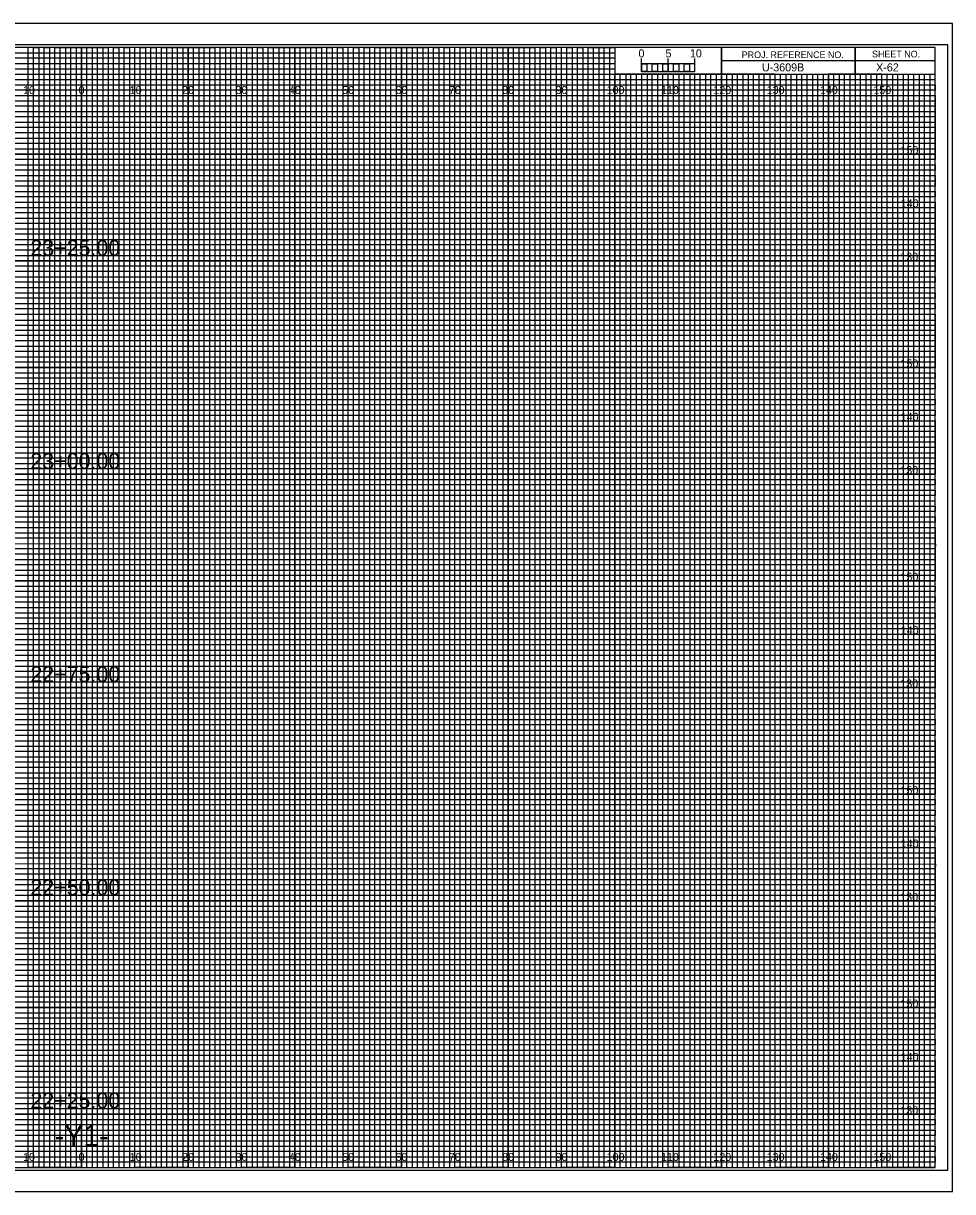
# Model space of a CAD drawing. Extents: x -13 to 323, y -5 to 2634.
# Drawn here: x 149.1 to 323.3, y 2195.5 to 2414.5 of the extents above; entities that cross this region are included whole.
import ezdxf

# ---------------------------------------------------------------- set-up
doc = ezdxf.new("R2010")
doc.units = 0
for name, color, linetype in [('Exist Cross Section Cell', 7, 'Continuous'), ('Exist XS Center Line Elevation Label', 7, 'Continuous'), ('Exist XS Ground Line', 7, 'Continuous'), ('Prop CMT Pvmt Course 1', 7, 'Continuous'), ('Prop CMT Pvmt Course 1 Wedge', 7, 'Continuous'), ('Prop CMT Pvmt Course 2', 7, 'Continuous'), ('Prop CMT Pvmt Course 2 Wedge', 7, 'Continuous'), ('Prop CMT Pvmt Course 3', 7, 'Continuous'), ('Prop CMT Pvmt Course 3 Wedge', 7, 'Continuous'), ('Prop CMT Pvmt Surface Shoulder', 7, 'Continuous'), ('Prop CMT Pvmt Wedge Surface 3', 7, 'Continuous'), ('Prop CMT Shld Paved Course 1', 7, 'Continuous'), ('Prop CMT Shld Paved Course 2', 7, 'Continuous'), ('Prop CMT Shld Paved Course 3', 7, 'Continuous'), ('Prop CMT Slope Grass', 7, 'Continuous'), ('Prop CMT Subgrade Earthwork', 7, 'Continuous'), ('Scratch_Level_0', 7, 'Continuous')]:
    doc.layers.add(name, color=color, linetype=linetype)

msp = doc.modelspace()

# ---------------------------------------------------------------- linework, layer by layer
at = {"layer": 'Exist XS Center Line Elevation Label'}
for points in [[(145, 2200), (155, 2200), (155, 2410), (165, 2410), (165, 2200), (175, 2200), (175, 2410), (185, 2410), (185, 2200), (195, 2200), (195, 2410), (205, 2410), (205, 2200), (215, 2200), (215, 2410), (225, 2410), (225, 2200), (235, 2200), (235, 2410), (245, 2410), (245, 2200), (255, 2200), (255, 2410), (259.93, 2410), (260, 2410), (260, 2405), (264.99, 2405), (264.99, 2200), (275, 2200), (275, 2405), (285, 2405), (285, 2200), (295, 2200), (295, 2405), (305, 2405), (305, 2200), (315, 2200), (315, 2405)], [(0, 2405), (275, 2405)], [(0, 2385), (320, 2385), (320, 2395), (0, 2395)], [(0, 2365), (320, 2365), (320, 2375), (0, 2375)], [(0, 2345), (320, 2345), (320, 2355), (0, 2355)], [(0, 2325), (320, 2325), (320, 2335), (0, 2335)], [(0, 2305), (320, 2305), (320, 2315), (0, 2315)], [(0, 2285), (320, 2285), (320, 2295), (0, 2295)], [(0, 2265), (320, 2265), (320, 2275), (0, 2275)], [(0, 2245), (320, 2245), (320, 2255), (0, 2255)], [(0, 2225), (320, 2225), (320, 2235), (0, 2235)], [(0, 2205), (320, 2205), (320, 2215), (0, 2215)]]:
    msp.add_lwpolyline(points, dxfattribs=at)
at = {"layer": 'Exist XS Ground Line'}
for p, q in [((150, 2410), (140, 2410)), ((150, 2200), (150, 2410)), ((170, 2410), (160, 2410)), ((160, 2410), (160, 2200)), ((170, 2200), (170, 2410)), ((190, 2410), (180, 2410)), ((180, 2410), (180, 2200)), ((190, 2200), (190, 2410)), ((210, 2410), (200, 2410)), ((200, 2410), (200, 2200)), ((210, 2200), (210, 2410)), ((230, 2410), (220, 2410)), ((220, 2410), (220, 2200)), ((230, 2200), (230, 2410)), ((250, 2410), (240, 2410)), ((240, 2410), (240, 2200)), ((250, 2200), (250, 2410)), ((260, 2410), (260, 2200)), ((270, 2200), (270, 2405)), ((290, 2405), (280, 2405)), ((280, 2405), (280, 2200)), ((290, 2200), (290, 2405)), ((310, 2405), (300, 2405)), ((300, 2405), (300, 2200)), ((310, 2200), (310, 2405)), ((160, 2200), (150, 2200)), ((180, 2200), (170, 2200)), ((200, 2200), (190, 2200)), ((220, 2200), (210, 2200)), ((240, 2200), (230, 2200)), ((260, 2200), (250, 2200)), ((280, 2200), (270, 2200)), ((300, 2200), (290, 2200)), ((320, 2200), (310, 2200)), ((320, 2200), (320, 2200))]:
    msp.add_line(p, q, dxfattribs=at)
for points in [[(0, 2400), (320, 2400), (320, 2390), (0, 2390)], [(0, 2380), (320, 2380), (320, 2370), (0, 2370)], [(0, 2360), (320, 2360), (320, 2350), (0, 2350)], [(0, 2340), (320, 2340), (320, 2330), (0, 2330)], [(0, 2320), (320, 2320), (320, 2310), (0, 2310)], [(0, 2300), (320, 2300), (320, 2290), (0, 2290)], [(0, 2280), (320, 2280), (320, 2270), (0, 2270)], [(0, 2260), (320, 2260), (320, 2250), (0, 2250)], [(0, 2240), (320, 2240), (320, 2230), (0, 2230)], [(0, 2220), (320, 2220), (320, 2210), (0, 2210)]]:
    msp.add_lwpolyline(points, dxfattribs=at)
at = {"layer": 'Prop CMT Pvmt Course 1'}
for p, q in [((265, 2405.49), (265, 2407.9)), ((265, 2406.9), (265, 2407.9)), ((270, 2405.49), (270, 2407.9)), ((275, 2405.49), (275, 2407.9)), ((275, 2406.9), (275, 2407.9))]:
    msp.add_line(p, q, dxfattribs=at)
for points in [[(275, 2406.9), (265, 2406.9), (265, 2405.49), (275, 2405.49)], [(265, 2406.9), (266, 2406.9), (266, 2405.49), (265, 2405.49)], [(267, 2406.9), (268, 2406.9), (268, 2405.49), (267, 2405.49)], [(269, 2406.9), (270, 2406.9), (270, 2405.49), (269, 2405.49)], [(271, 2406.9), (272, 2406.9), (272, 2405.49), (271, 2405.49)], [(273, 2406.9), (274, 2406.9), (274, 2405.49), (273, 2405.49)]]:
    msp.add_lwpolyline(points, close=True, dxfattribs=at)
at = {"layer": 'Prop CMT Pvmt Surface Shoulder'}
for p, q in [((267, 2405), (266.01, 2405)), ((266.01, 2405), (266.01, 2200)), ((267, 2200), (267, 2405)), ((269, 2405), (268, 2405)), ((268, 2405), (268, 2200)), ((269, 2200), (269, 2405)), ((266.01, 2200), (265, 2200)), ((268, 2200), (267, 2200))]:
    msp.add_line(p, q, dxfattribs=at)
for points in [[(150, 2200), (151, 2200), (151, 2410), (152, 2410), (152, 2200)], [(152, 2200), (153, 2200), (153, 2410), (154, 2410), (154, 2200)], [(155, 2200), (156, 2200), (156, 2410), (157, 2410), (157, 2200)], [(157, 2200), (158, 2200), (158, 2410), (159, 2410), (159, 2200)], [(160, 2200), (161, 2200), (161, 2410), (162, 2410), (162, 2200)], [(162, 2200), (163, 2200), (163, 2410), (164, 2410), (164, 2200)], [(165, 2200), (166, 2200), (166, 2410), (167, 2410), (167, 2200)], [(167, 2200), (168, 2200), (168, 2410), (169, 2410), (169, 2200)], [(170, 2200), (171, 2200), (171, 2410), (172, 2410), (172, 2200)], [(172, 2200), (173, 2200), (173, 2410), (174, 2410), (174, 2200)], [(175, 2200), (176, 2200), (176, 2410), (177, 2410), (177, 2200)], [(177, 2200), (178, 2200), (178, 2410), (179, 2410), (179, 2200)], [(180, 2200), (181, 2200), (181, 2410), (182, 2410), (182, 2200)], [(182, 2200), (183, 2200), (183, 2410), (184, 2410), (184, 2200)], [(185, 2200), (186, 2200), (186, 2410), (187, 2410), (187, 2200)], [(187, 2200), (188, 2200), (188, 2410), (189, 2410), (189, 2200)], [(190, 2200), (191, 2200), (191, 2410), (192, 2410), (192, 2200)], [(192, 2200), (193, 2200), (193, 2410), (194, 2410), (194, 2200)], [(195, 2200), (196, 2200), (196, 2410), (197, 2410), (197, 2200)], [(197, 2200), (198, 2200), (198, 2410), (199, 2410), (199, 2200)], [(200, 2200), (201, 2200), (201, 2410), (202, 2410), (202, 2200)], [(202, 2200), (203, 2200), (203, 2410), (204, 2410), (204, 2200)], [(205, 2200), (206, 2200), (206, 2410), (207, 2410), (207, 2200)], [(207, 2200), (208, 2200), (208, 2410), (209, 2410), (209, 2200)], [(210, 2200), (211, 2200), (211, 2410), (212, 2410), (212, 2200)], [(212, 2200), (213, 2200), (213, 2410), (214, 2410), (214, 2200)], [(215, 2200), (216, 2200), (216, 2410), (217, 2410), (217, 2200)], [(217, 2200), (218, 2200), (218, 2410), (219, 2410), (219, 2200)], [(220, 2200), (221, 2200), (221, 2410), (222, 2410), (222, 2200)], [(222, 2200), (223, 2200), (223, 2410), (224, 2410), (224, 2200)], [(225, 2200), (226, 2200), (226, 2410), (227, 2410), (227, 2200)], [(227, 2200), (228, 2200), (228, 2410), (229, 2410), (229, 2200)], [(230, 2200), (231, 2200), (231, 2410), (232, 2410), (232, 2200)], [(232, 2200), (233, 2200), (233, 2410), (234, 2410), (234, 2200)], [(235, 2200), (236, 2200), (236, 2410), (237, 2410), (237, 2200)], [(237, 2200), (238, 2200), (238, 2410), (239, 2410), (239, 2200)], [(240, 2200), (241, 2200), (241, 2410), (242, 2410), (242, 2200)], [(242, 2200), (243, 2200), (243, 2410), (244, 2410), (244, 2200)], [(245, 2200), (246, 2200), (246, 2410), (247, 2410), (247, 2200)], [(247, 2200), (248, 2200), (248, 2410), (249, 2410), (249, 2200)], [(250, 2200), (251, 2200), (251, 2410), (252, 2410), (252, 2200)], [(252, 2200), (253, 2200), (253, 2410), (254, 2410), (254, 2200)], [(255, 2200), (256, 2200), (256, 2410), (257, 2410), (257, 2200)], [(257, 2200), (258, 2200), (258, 2410), (259, 2410), (259, 2200)], [(260, 2200), (261, 2200), (261, 2405), (262.02, 2405), (262.02, 2200)], [(262, 2200), (263, 2200), (263, 2405), (263.99, 2405), (263.99, 2200)], [(270, 2200), (270.98, 2200), (270.98, 2405), (272, 2405), (272, 2200)], [(272, 2200), (273, 2200), (273, 2405), (274.05, 2405), (274.05, 2200)], [(275, 2200), (276, 2200), (276, 2405), (277, 2405), (277, 2200)], [(277, 2200), (278, 2200), (278, 2405), (279, 2405), (279, 2200)], [(280, 2200), (281, 2200), (281, 2405), (282, 2405), (282, 2200)], [(282, 2200), (283, 2200), (283, 2405), (284, 2405), (284, 2200)], [(285, 2200), (286, 2200), (286, 2405), (287, 2405), (287, 2200)], [(287, 2200), (288, 2200), (288, 2405), (289, 2405), (289, 2200)], [(290, 2200), (291, 2200), (291, 2405), (292, 2405), (292, 2200)], [(292, 2200), (293, 2200), (293, 2405), (294, 2405), (294, 2200)], [(295, 2200), (296, 2200), (296, 2405), (297, 2405), (297, 2200)], [(297, 2200), (298, 2200), (298, 2405), (299, 2405), (299, 2200)], [(300, 2200), (301, 2200), (301, 2405), (302, 2405), (302, 2200)], [(302, 2200), (303, 2200), (303, 2405), (304, 2405), (304, 2200)], [(305, 2200), (306, 2200), (306, 2405), (307, 2405), (307, 2200)], [(307, 2200), (308, 2200), (308, 2405), (309, 2405), (309, 2200)], [(310, 2200), (311, 2200), (311, 2405), (312, 2405), (312, 2200)], [(312, 2200), (313, 2200), (313, 2405), (314, 2405), (314, 2200)], [(315, 2200), (316, 2200), (316, 2405), (317, 2405), (317, 2200)], [(317, 2200), (318, 2200), (318, 2405), (319, 2405), (319, 2200)]]:
    msp.add_lwpolyline(points, dxfattribs=at)
at = {"layer": 'Prop CMT Pvmt Wedge Surface 3'}
for p, q in [((305, 2410), (305, 2405)), ((305, 2405), (305, 2410)), ((280, 2407.5), (280, 2405)), ((320, 2407.49), (280, 2407.49)), ((280, 2405), (320, 2405))]:
    msp.add_line(p, q, dxfattribs=at)
for points in [[(320, 2410), (0, 2410), (0, 2200), (320, 2200)], [(280, 2410), (260, 2410), (260, 2405.03), (280, 2405.03)], [(320, 2410), (280, 2410), (280, 2405), (320, 2405)]]:
    msp.add_lwpolyline(points, close=True, dxfattribs=at)
at = {"layer": 'Prop CMT Shld Paved Course 1'}
for p, q in [((150, 2200), (150, 2410)), ((160, 2200), (160, 2410)), ((170, 2200), (170, 2410)), ((180, 2200), (180, 2410)), ((190, 2200), (190, 2410)), ((200, 2200), (200, 2410)), ((210, 2200), (210, 2410)), ((220, 2200), (220, 2410)), ((230, 2200), (230, 2410)), ((240, 2200), (240, 2410)), ((250, 2200), (250, 2410)), ((260, 2200), (260, 2404.69)), ((270, 2200), (270, 2404.69)), ((280, 2200), (280, 2404.69)), ((290, 2200), (290, 2404.69)), ((300, 2200), (300, 2404.69)), ((310, 2200), (310, 2404.69)), ((0, 2400), (320, 2400)), ((0, 2390), (320, 2390)), ((0, 2380), (320, 2380)), ((0, 2370), (320, 2370)), ((0, 2360), (320, 2360)), ((0, 2350), (320, 2350)), ((0, 2340), (320, 2340)), ((0, 2330), (320, 2330)), ((0, 2320), (320, 2320)), ((0, 2310), (320, 2310)), ((0, 2300), (320, 2300)), ((0, 2290), (320, 2290)), ((0, 2280), (320, 2280)), ((0, 2270), (320, 2270)), ((0, 2260), (320, 2260)), ((0, 2250), (320, 2250)), ((0, 2240), (320, 2240)), ((0, 2230), (320, 2230)), ((0, 2220), (320, 2220)), ((0, 2210), (320, 2210))]:
    msp.add_line(p, q, dxfattribs=at)
at = {"layer": 'Prop CMT Shld Paved Course 2'}
for p, q in [((323.3, 2414.5), (-13.4, 2414.5)), ((-13.4, 2195.5), (323.3, 2195.5))]:
    msp.add_line(p, q, dxfattribs=at)
at = {"layer": 'Prop CMT Slope Grass'}
msp.add_lwpolyline([(-10.8, 2199.5), (322.4, 2199.5), (322.4, 2410.5), (-10.8, 2410.5)], close=True, dxfattribs=at)
at = {"layer": 'Prop CMT Subgrade Earthwork'}
msp.add_lwpolyline([(-13.4, 2195.5), (323.3, 2195.5), (323.3, 2414.5), (-13.4, 2414.5)], close=True, dxfattribs=at)
at = {"layer": 'Scratch_Level_0'}
for p, q in [((0, 2409), (260, 2409)), ((260, 2409), (260, 2407.98)), ((260, 2407.98), (0, 2407.98)), ((0, 2407), (260, 2407)), ((260, 2407), (260, 2405.89)), ((260, 2405.89), (0, 2405.89)), ((0, 2404), (320, 2404))]:
    msp.add_line(p, q, dxfattribs=at)
for points in [[(0, 2403), (270, 2403), (320, 2403), (320, 2402), (0, 2402)], [(0, 2401), (320, 2401), (320, 2399), (0, 2399)], [(0, 2398), (320, 2398), (320, 2397), (0, 2396.98)], [(0, 2396), (320, 2396), (320, 2394), (0, 2394)], [(0, 2393), (320, 2393), (320, 2392), (0, 2392)], [(0, 2391), (320, 2391), (320, 2389), (0, 2389)], [(0, 2388), (320, 2388), (320, 2387), (0, 2387)], [(0, 2386), (320, 2386), (320, 2384), (0, 2384)], [(0, 2383), (320, 2383), (320, 2382), (0, 2382)], [(0, 2381), (320, 2381), (320, 2379), (0, 2379)], [(0, 2378), (320, 2378), (320, 2377), (0, 2377)], [(0, 2376), (320, 2376), (320, 2373.95), (320, 2373), (320, 2372), (0, 2372)], [(0, 2374), (320, 2374), (320, 2373), (0, 2373)], [(0, 2371), (320, 2371), (320, 2369), (0, 2369.03)], [(0, 2369.03), (320, 2369), (320, 2368), (0, 2368)], [(0, 2367), (320, 2367), (320, 2366), (0, 2366)], [(0, 2364), (320, 2364), (320, 2363), (0, 2363)], [(0, 2362), (320, 2362), (320, 2361), (0, 2361)], [(-0.07, 2358.89), (320, 2358.89), (320, 2357.88), (-0.07, 2357.88)], [(0, 2357), (320, 2357), (320, 2356), (0, 2356)], [(0, 2354), (320, 2354), (320, 2353), (0, 2353)], [(0, 2352), (320, 2352), (320, 2351), (0, 2351)], [(0, 2349), (320, 2349), (320, 2348), (0, 2348)], [(0, 2347), (320, 2347), (320, 2346), (0, 2346)], [(0, 2344), (320, 2344), (320, 2343), (0, 2343)], [(0, 2342), (320, 2342), (320, 2341), (0, 2341)], [(0, 2339), (320, 2339), (319.99, 2337.98), (0, 2338)], [(0, 2337), (320, 2337), (320, 2336), (0, 2336)], [(0, 2334), (320, 2334), (320, 2333), (0, 2333)], [(0, 2332), (320, 2332), (320, 2331), (0, 2331)], [(0, 2329), (320, 2329), (320, 2328), (0, 2328)], [(0, 2327), (320, 2327), (320, 2326), (0, 2326)], [(0, 2324), (320, 2324), (320, 2323), (0, 2323)], [(0, 2322), (320, 2322), (320, 2321), (0, 2321)], [(0, 2319), (320, 2319), (320, 2318), (0, 2318)], [(0, 2316.99), (320.07, 2316.91), (320, 2316), (0, 2316)], [(0, 2314), (320, 2314), (320, 2313), (0, 2313)], [(0, 2312), (320, 2312), (320, 2311), (0, 2311)], [(0, 2309), (320, 2309), (320, 2308), (0, 2308)], [(0, 2307), (320, 2307), (320, 2306), (0, 2306)], [(0, 2304), (320, 2304), (320, 2303), (0, 2303)], [(0, 2302), (320, 2302), (320, 2301), (0, 2301)], [(0, 2299), (320, 2299), (320, 2298), (0, 2298)], [(0, 2297), (320, 2297), (320, 2296), (0, 2296)], [(0, 2294), (320, 2294), (320, 2293), (0, 2293)], [(0, 2292), (320, 2292), (320, 2291), (0, 2291)], [(0, 2289), (320, 2289), (320, 2288), (0, 2288)], [(0, 2287), (320, 2287), (320, 2286), (0, 2286)], [(0, 2284), (320, 2284), (320, 2283), (0, 2283)], [(0, 2282), (320, 2282), (320, 2281), (0, 2281)], [(0, 2279), (320, 2279), (319.99, 2277.98), (0, 2278)], [(0, 2277), (320, 2277), (320, 2276), (0, 2276)], [(0, 2274), (320, 2274), (320, 2273), (0, 2273)], [(0, 2272), (320, 2272), (320, 2271), (0, 2271)], [(0, 2269), (320, 2269), (320, 2268), (0, 2268)], [(0, 2267), (320, 2267), (320, 2266), (0, 2266)], [(0, 2264), (320, 2264), (320, 2263), (0, 2263)], [(0, 2262), (320, 2262), (320, 2261), (0, 2261)], [(0, 2259), (320, 2259), (320, 2258), (0, 2258)], [(0, 2256.99), (320.07, 2256.91), (320, 2256), (0, 2256)], [(0, 2254), (320, 2254), (320, 2253), (0, 2253)], [(0, 2252), (320, 2252), (320, 2251), (0, 2251)], [(0, 2249), (320, 2249), (320, 2248), (0, 2248)], [(0, 2247), (320, 2247), (320, 2246), (0, 2246)], [(0, 2244), (320, 2244), (320, 2243), (0, 2243)], [(0, 2242), (320, 2242), (320, 2241), (0, 2241)], [(0, 2239), (320, 2239), (320, 2238), (0, 2238)], [(0, 2237), (320, 2237), (320, 2236), (0, 2236)], [(0, 2234), (320, 2234), (320, 2233), (0, 2233)], [(0, 2232), (320, 2232), (320, 2231), (0, 2231)], [(0, 2229), (320, 2229), (320, 2228), (0, 2228)], [(0, 2227), (320, 2227), (320, 2226), (0, 2226)], [(0, 2224), (320, 2224), (320, 2223), (0, 2223)], [(0, 2222), (320, 2222), (320, 2221), (0, 2221)], [(0, 2219), (320, 2219), (320, 2218), (0, 2218)], [(0, 2217), (320, 2217), (320, 2216), (0, 2216)], [(0, 2214), (320, 2214), (320, 2213), (0, 2213)], [(0, 2212), (320, 2212), (320, 2211), (0, 2211)], [(0, 2209), (320, 2209), (320, 2208), (0, 2208)], [(0, 2207), (320, 2207), (320, 2206), (0, 2206)], [(0, 2204), (320, 2204), (320, 2203), (0, 2203)], [(0, 2202), (320, 2202), (320, 2201), (0, 2201)]]:
    msp.add_lwpolyline(points, dxfattribs=at)

# ---------------------------------------------------------------- texts
at = {"layer": 'Exist Cross Section Cell'}
for s, p in [('10', (149.04, 2401.25)), ('0', (159.45, 2401.25)), ('0', (159.45, 2401.25)), ('10', (169.04, 2401.25)), ('20', (178.86, 2401.25)), ('30', (188.86, 2401.25)), ('40', (198.86, 2401.25)), ('50', (208.86, 2401.25)), ('60', (218.86, 2401.25)), ('70', (228.86, 2401.25)), ('80', (238.86, 2401.25)), ('90', (248.86, 2401.25)), ('100', (258.44, 2401.25)), ('110', (268.62, 2401.25)), ('120', (278.44, 2401.25)), ('130', (288.44, 2401.25)), ('140', (298.44, 2401.25)), ('150', (308.44, 2401.25)), ('10', (149.04, 2201.25)), ('0', (159.45, 2201.25)), ('0', (159.45, 2201.25)), ('10', (169.04, 2201.25)), ('20', (178.86, 2201.25)), ('30', (188.86, 2201.25)), ('40', (198.86, 2201.25)), ('50', (208.86, 2201.25)), ('60', (218.86, 2201.25)), ('70', (228.86, 2201.25)), ('80', (238.86, 2201.25)), ('90', (248.86, 2201.25)), ('100', (258.44, 2201.25)), ('110', (268.62, 2201.25)), ('120', (278.44, 2201.25)), ('130', (288.44, 2201.25)), ('140', (298.44, 2201.25)), ('150', (308.44, 2201.25))]:
    msp.add_text(s, height=1.5, dxfattribs=at).set_placement(p)
at = {"layer": 'Prop CMT Pvmt Course 1'}
msp.add_text('0', height=1.5, dxfattribs=at).set_placement((264.41, 2408.12))
at = {"layer": 'Prop CMT Pvmt Course 1 Wedge'}
msp.add_text('U-3609B', height=1.5, dxfattribs=at).set_placement((287.56, 2405.5))
at = {"layer": 'Prop CMT Pvmt Course 2'}
for s, p in [('23+25.00', (150.41, 2370.91)), ('23+00.00', (150.41, 2330.96)), ('22+75.00', (150.41, 2291)), ('22+50.00', (150.41, 2251.04)), ('22+25.00', (150.41, 2211.1))]:
    msp.add_text(s, height=3, dxfattribs=at).set_placement(p)
at = {"layer": 'Prop CMT Pvmt Course 2 Wedge'}
msp.add_text('-Y1-', height=4, dxfattribs=at).set_placement((154.99, 2204))
at = {"layer": 'Prop CMT Pvmt Course 3'}
msp.add_text('X-62', height=1.5, dxfattribs=at).set_placement((308.96, 2405.5))
at = {"layer": 'Prop CMT Pvmt Course 3 Wedge'}
for s, p in [('5', (269.47, 2408.12)), ('10', (274.04, 2408.12))]:
    msp.add_text(s, height=1.5, dxfattribs=at).set_placement(p)
at = {"layer": 'Prop CMT Pvmt Wedge Surface 3'}
for s, p in [('PROJ. REFERENCE NO.', (283.77, 2407.99)), ('SHEET NO.', (308.19, 2408.12))]:
    msp.add_text(s, height=1.25, dxfattribs=at).set_placement(p)
at = {"layer": 'Prop CMT Shld Paved Course 3'}
for s, p in [('150', (313.52, 2390)), ('140', (313.57, 2380)), ('130', (313.49, 2370)), ('150', (313.52, 2350)), ('140', (313.57, 2340)), ('130', (313.49, 2330)), ('150', (313.52, 2310)), ('140', (313.57, 2300)), ('130', (313.49, 2290)), ('150', (313.52, 2270)), ('140', (313.57, 2260)), ('130', (313.49, 2250)), ('150', (313.52, 2230)), ('140', (313.57, 2220)), ('130', (313.49, 2210))]:
    msp.add_text(s, height=1.5, dxfattribs=at).set_placement(p)

doc.saveas('drawing.dxf')
